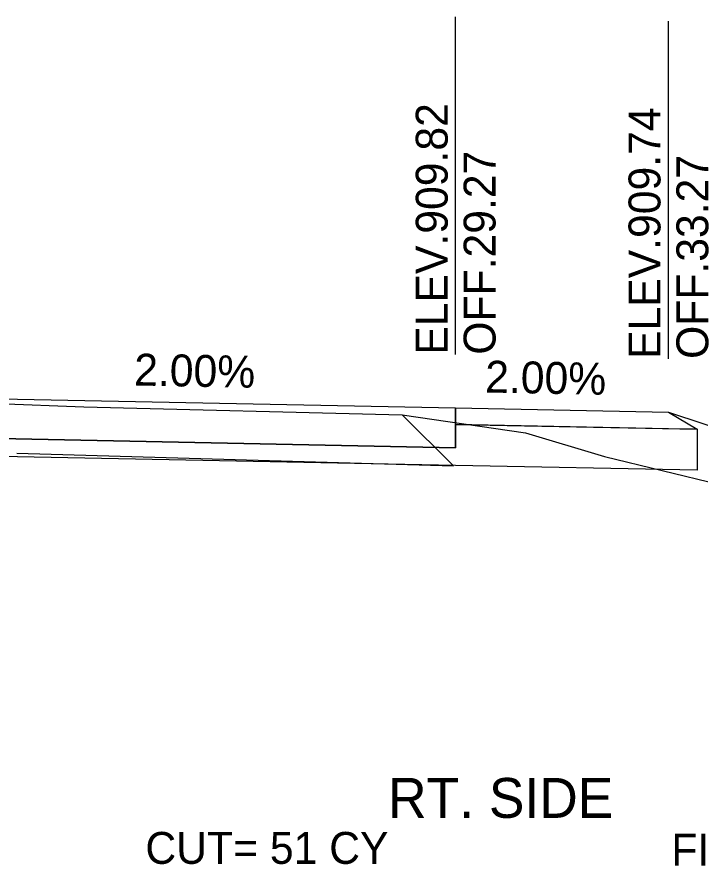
# Model space of a CAD drawing. Extents: x -4 to 359, y 0 to 1436.
# Drawn here: x 273.52 to 286.36, y 1276.17 to 1292.13 of the extents above; entities that cross this region are included whole.
import ezdxf

# ---------------------------------------------------------------- set-up
doc = ezdxf.new("R2010")
doc.units = 0
for name, color, linetype in [('XS-Existing subsurface-shoulder', 7, 'Continuous'), ('XS-Existing surface-ground', 7, 'Continuous'), ('XS-Proposed Finish Grade', 7, 'Continuous'), ('XS-Proposed subsurface-aggregate layer 1', 7, 'Continuous'), ('XS-Proposed surface-ground', 7, 'Continuous'), ('XS-Proposed surface-pavement', 7, 'Continuous'), ('XS-Proposed surface-shoulder', 7, 'Continuous'), ('XS-Text-earthwork labels', 7, 'Continuous'), ('XS-Text-pavement elevation', 7, 'Continuous'), ('XS-Text-pavement slope', 7, 'Continuous'), ('XS-Text-profile report', 7, 'Continuous'), ('XS-Text-shoulder elevation', 7, 'Continuous'), ('XS-Text-shoulder slope', 7, 'Continuous'), ('XS-Text-tie offset', 7, 'Continuous')]:
    doc.layers.add(name, color=color, linetype=linetype)

msp = doc.modelspace()

# ---------------------------------------------------------------- linework, layer by layer
at = {"layer": 'XS-Existing subsurface-shoulder'}
for p in [(280.766, 1284.653), (273.524, 1283.931)]:
    msp.add_line(p, (281.728, 1283.691), dxfattribs=at)
at = {"layer": 'XS-Existing surface-ground'}
for p, q in [((272.573, 1284.882), (274.779, 1284.804)), ((274.779, 1284.804), (280.766, 1284.653)), ((280.766, 1284.653), (283.081, 1284.311)), ((283.081, 1284.311), (284.572, 1283.867)), ((284.572, 1283.867), (291.075, 1282.286))]:
    msp.add_line(p, q, dxfattribs=at)
at = {"layer": 'XS-Proposed Finish Grade'}
for points in [[(272.573, 1284.966), (281.771, 1284.782)], [(281.771, 1284.782), (285.771, 1284.702)]]:
    msp.add_lwpolyline(points, dxfattribs=at)
at = {"layer": 'XS-Proposed subsurface-aggregate layer 1'}
for points in [[(281.771, 1284.032), (281.771, 1284.469)], [(281.771, 1284.469), (286.309, 1284.378)], [(286.309, 1284.378), (286.309, 1283.608)], [(272.573, 1284.216), (281.771, 1284.032)], [(286.309, 1283.608), (281.771, 1283.698), (272.573, 1283.882)]]:
    msp.add_lwpolyline(points, dxfattribs=at)
at = {"layer": 'XS-Proposed surface-ground'}
msp.add_lwpolyline([(285.771, 1284.702), (291.771, 1282.722), (295.771, 1282.722), (296.455, 1283.064)], dxfattribs=at)
at = {"layer": 'XS-Proposed surface-pavement'}
for points in [[(272.573, 1284.966), (281.771, 1284.782)], [(281.771, 1284.782), (281.771, 1284.032)], [(281.771, 1284.032), (272.573, 1284.216)]]:
    msp.add_lwpolyline(points, dxfattribs=at)
at = {"layer": 'XS-Proposed surface-shoulder'}
for points in [[(281.771, 1284.782), (285.771, 1284.702), (286.309, 1284.378)], [(281.771, 1284.469), (281.771, 1284.782)], [(286.309, 1284.378), (285.771, 1284.389), (281.771, 1284.469)]]:
    msp.add_lwpolyline(points, dxfattribs=at)
at = {"layer": 'XS-Text-tie offset'}
for p, q in [((281.771, 1285.782), (281.771, 1292.132)), ((285.771, 1285.702), (285.771, 1292.052))]:
    msp.add_line(p, q, dxfattribs=at)

# ---------------------------------------------------------------- texts
at = {"layer": 'XS-Text-earthwork labels'}
for s, height, p in [('RT. SIDE', 0.75, (280.501, 1277.072)), (' CUT= 51 CY           ', 0.6, (275.715, 1276.207)), ('FILL= 5 CY           ', 0.6, (285.826, 1276.175))]:
    msp.add_text(s, height=height, dxfattribs=at).set_placement(p)
at = {"layer": 'XS-Text-pavement elevation'}
for s, p in [('ELEV.909.82', (281.621, 1285.782)), ('OFF.29.27', (282.521, 1285.782))]:
    msp.add_text(s, height=0.6, rotation=90, dxfattribs=at).set_placement(p)
at = {"layer": 'XS-Text-pavement slope'}
msp.add_text('2.00%', height=0.6, rotation=358.8542, dxfattribs=at).set_placement((275.722, 1285.203))
at = {"layer": 'XS-Text-profile report'}
for s, p in [('Pvmt_Surf_Conc_T1_R', (281.755, 1284.781)), ('Shldr_Surf_Asph_T11', (285.755, 1284.701)), ('Shldr_Surf_Asph_B13', (281.755, 1284.468)), ('Shldr_Surf_Asph_B11', (285.755, 1284.388)), ('Shldr_Surf_Asph_B21', (286.294, 1284.378)), ('Pvmt_Surf_Conc_B1_R', (281.755, 1284.031)), ('Agg_Layer_1_B11', (281.759, 1283.698)), ('Agg_Layer_1_B12', (286.297, 1283.607))]:
    msp.add_text(s, height=0.00167, dxfattribs=at).set_placement(p)
at = {"layer": 'XS-Text-shoulder elevation'}
for s, p in [('ELEV.909.74', (285.621, 1285.702)), ('OFF.33.27', (286.521, 1285.702))]:
    msp.add_text(s, height=0.6, rotation=90, dxfattribs=at).set_placement(p)
at = {"layer": 'XS-Text-shoulder slope'}
msp.add_text('2.00%', height=0.6, rotation=358.8542, dxfattribs=at).set_placement((282.321, 1285.071))

doc.saveas('drawing.dxf')
